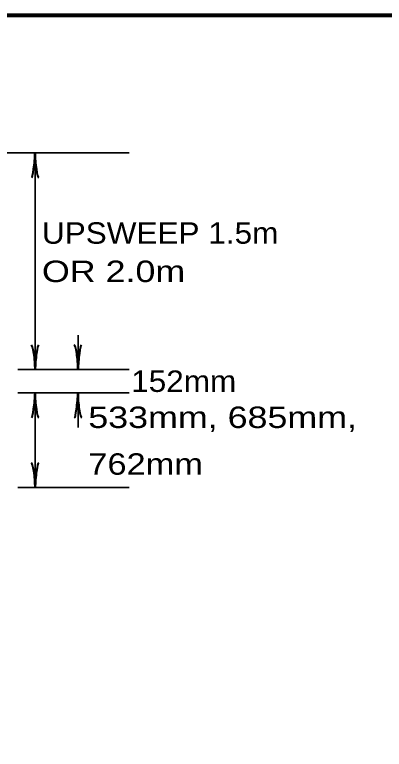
# Model space of a CAD drawing. Extents: x -20 to 693, y -19 to 435.
# Drawn here: x 139.5 to 183.3, y 342.3 to 429.4 of the extents above; entities that cross this region are included whole.
import ezdxf

# ---------------------------------------------------------------- set-up
doc = ezdxf.new("R2010")
doc.units = 0
doc.layers.add('1', color=7, linetype='Continuous', lineweight=53)

msp = doc.modelspace()

# ---------------------------------------------------------------- linework, layer by layer
at = {"layer": '1', "lineweight": 35}
for p, q in [((78.243, 412.967), (153.063, 412.967)), ((141.903, 387.307), (141.903, 412.967)), ((146.983, 387.307), (146.983, 391.367)), ((139.863, 387.307), (153.063, 387.307)), ((139.863, 384.527), (153.063, 384.527)), ((141.903, 373.327), (141.903, 384.527)), ((146.983, 380.447), (146.983, 384.527)), ((139.863, 373.327), (153.063, 373.327))]:
    msp.add_line(p, q, dxfattribs=at)
at = {"layer": '1', "lineweight": 158}
msp.add_lwpolyline([(687.723, 429.353), (27.973, 429.27), (28.056, -9.063)], dxfattribs=at)
at = {"layer": '1', "lineweight": 40}
for centre, major_axis, ratio, start_param, end_param in [((141.679, 411.825), (-0.178, -1.785), 0.07063, 6.282307, 8.559703), ((141.679, 411.825), (-0.178, -1.785), 0.07063, 6.282307, 8.559703), ((142.175, 411.854), (-0.159, 1.814), 0.122415, 0.896353, 3.141593), ((142.175, 411.854), (-0.159, 1.814), 0.122415, 0.896353, 3.141593), ((141.613, 388.408), (0.159, -1.814), 0.122415, 0.896353, 3.141593), ((141.613, 388.408), (0.159, -1.814), 0.122415, 0.896353, 3.141593), ((142.109, 388.438), (0.178, 1.785), 0.07063, 6.282307, 8.559703), ((142.109, 388.438), (0.178, 1.785), 0.07063, 6.282307, 8.559703), ((146.693, 388.408), (0.159, -1.814), 0.122415, 0.896353, 3.141593), ((146.693, 388.408), (0.159, -1.814), 0.122415, 0.896353, 3.141593), ((147.189, 388.438), (0.178, 1.785), 0.07063, 6.282307, 8.559703), ((147.189, 388.438), (0.178, 1.785), 0.07063, 6.282307, 8.559703), ((141.679, 383.379), (-0.178, -1.785), 0.07063, 6.282307, 8.559703), ((141.679, 383.379), (-0.178, -1.785), 0.07063, 6.282307, 8.559703), ((142.175, 383.409), (-0.159, 1.814), 0.122415, 0.896353, 3.141593), ((142.175, 383.409), (-0.159, 1.814), 0.122415, 0.896353, 3.141593), ((146.759, 383.379), (-0.178, -1.785), 0.07063, 6.282307, 8.559703), ((146.759, 383.379), (-0.178, -1.785), 0.07063, 6.282307, 8.559703), ((147.255, 383.409), (-0.159, 1.814), 0.122415, 0.896353, 3.141593), ((147.255, 383.409), (-0.159, 1.814), 0.122415, 0.896353, 3.141593), ((141.613, 374.437), (0.159, -1.814), 0.122415, 0.896353, 3.141593), ((141.613, 374.437), (0.159, -1.814), 0.122415, 0.896353, 3.141593), ((142.109, 374.467), (0.178, 1.785), 0.07063, 6.282307, 8.559703), ((142.109, 374.467), (0.178, 1.785), 0.07063, 6.282307, 8.559703)]:
    msp.add_ellipse(centre, major_axis=major_axis, ratio=ratio, start_param=start_param, end_param=end_param, dxfattribs=at)

# ---------------------------------------------------------------- texts
at = {"layer": '1'}
for s, width, p in [('UPSWEEP 1.5m', 1.1, (142.703, 402.207)), ('OR 2.0m', 1.25, (142.703, 397.666)), ('152mm', 1.1, (153.283, 384.647)), ('533mm, 685mm,', 1.25, (148.201, 380.369)), ('762mm', 1.2, (148.201, 374.829))]:
    msp.add_text(s, height=2.54, dxfattribs=dict(at, width=width)).set_placement(p)

doc.saveas('drawing.dxf')
